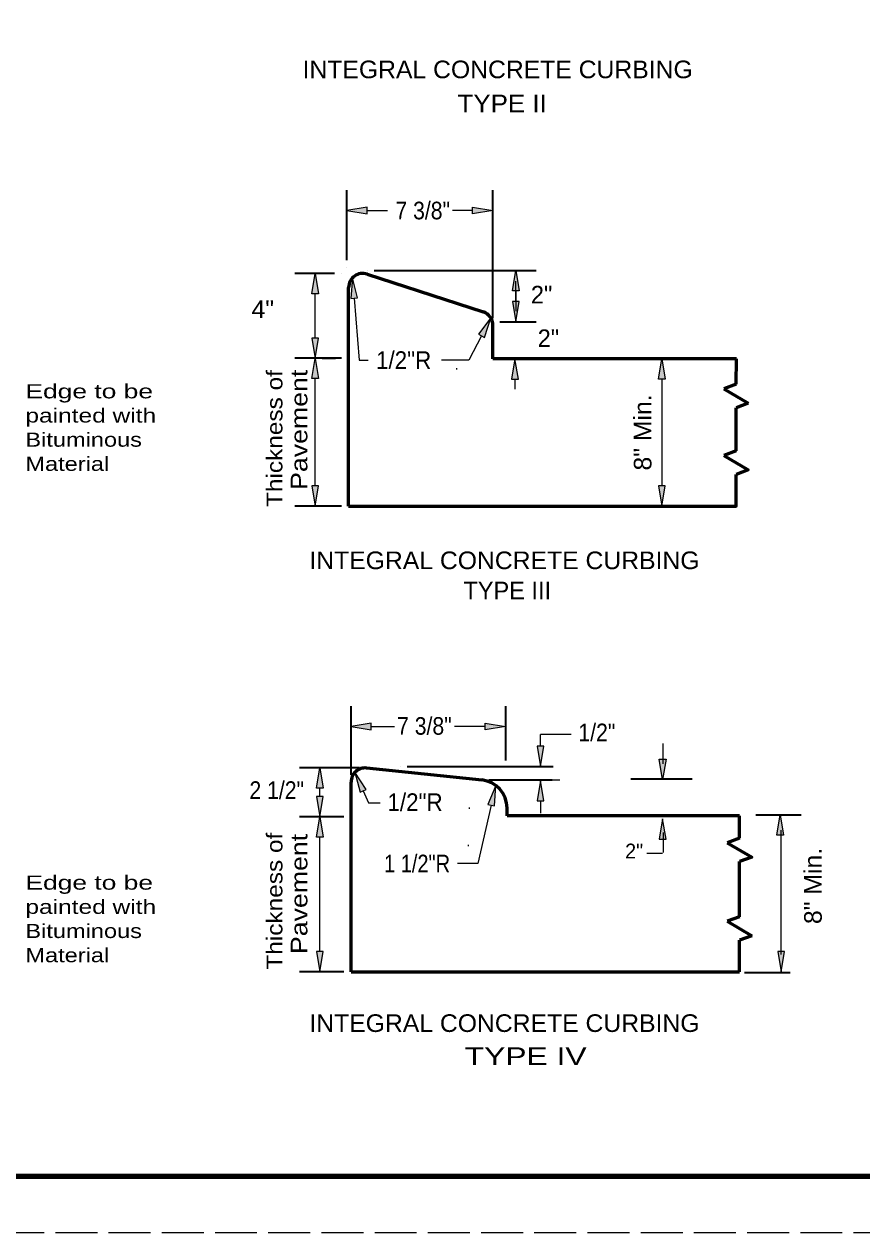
# Model space of a CAD drawing. Extents: x 36.6 to 71.9, y 0.8 to 22.8.
# Drawn here: x 47.06 to 54.49, y 0.78 to 11.49 of the extents above; entities that cross this region are included whole.
import ezdxf

# ---------------------------------------------------------------- set-up
doc = ezdxf.new("R2010")
doc.units = 0
doc.header["$LTSCALE"] = 0.062
doc.linetypes.add('LONG_DASHED', pattern=[7.5, 6, -1.5])
for name, color, linetype, lineweight in [('1', 7, 'Continuous', 13), ('3', 7, 'Continuous', 25), ('8', 7, 'Continuous', 13)]:
    doc.layers.add(name, color=color, linetype=linetype, lineweight=lineweight)

msp = doc.modelspace()

# ---------------------------------------------------------------- hatches: boundary and pattern name
at = {"layer": '1'}
for points in [[(50.10725, 9.80917), (50.10725, 9.86917), (49.92725, 9.83917), (49.92725, 9.83917)], [(51.04242, 9.80917), (51.04242, 9.86917), (51.22242, 9.83917), (51.22242, 9.83917)], [(49.67483, 9.10217), (49.61483, 9.10217), (49.64483, 9.28217), (49.64483, 9.28217)], [(51.45583, 9.12683), (51.39583, 9.12683), (51.42583, 9.30683), (51.42583, 9.30683)], [(51.45583, 9.03275), (51.39583, 9.03275), (51.42583, 8.85283), (51.42583, 8.85283)], [(49.67483, 8.70908), (49.61483, 8.70908), (49.64483, 8.529), (49.64483, 8.529)], [(49.67483, 8.34908), (49.61483, 8.34908), (49.64483, 8.529), (49.64483, 8.529)], [(52.75033, 8.34358), (52.69033, 8.34358), (52.72033, 8.52367), (52.72033, 8.52367)], [(49.67483, 7.40017), (49.61483, 7.40017), (49.64483, 7.22017), (49.64483, 7.22017)], [(52.75033, 7.40017), (52.69033, 7.40017), (52.72033, 7.22017), (52.72033, 7.22017)], [(50.14383, 5.23517), (50.14383, 5.29517), (49.96383, 5.26517), (49.96383, 5.26517)], [(51.15408, 5.23517), (51.15408, 5.29517), (51.33408, 5.26517), (51.33408, 5.26517)], [(51.67525, 5.09142), (51.61525, 5.09142), (51.64525, 4.91142), (51.64525, 4.91142)], [(52.69808, 4.97658), (52.75808, 4.97658), (52.72808, 4.79667), (52.72808, 4.79667)], [(49.71608, 4.71817), (49.65608, 4.71817), (49.68608, 4.89817), (49.68608, 4.89817)], [(51.61533, 4.60817), (51.67533, 4.60817), (51.64533, 4.78808), (51.64533, 4.78808)], [(49.71608, 4.6465), (49.65608, 4.6465), (49.68608, 4.4665), (49.68608, 4.4665)], [(49.71608, 4.2865), (49.65608, 4.2865), (49.68608, 4.4665), (49.68608, 4.4665)], [(52.69808, 4.26808), (52.75808, 4.26808), (52.72808, 4.448), (52.72808, 4.448)], [(53.80083, 4.30375), (53.74083, 4.30375), (53.77083, 4.48367), (53.77083, 4.48367)], [(49.71608, 3.27167), (49.65608, 3.27167), (49.68608, 3.09167), (49.68608, 3.09167)], [(53.80975, 3.27158), (53.74975, 3.27158), (53.77975, 3.09158), (53.77975, 3.09158)]]:
    msp.add_hatch(color=256, dxfattribs=at).paths.add_polyline_path(points)
at = {"layer": '3'}
for points in [[(49.96092, 9.05975), (50.02075, 9.06483), (49.97575, 9.24167), (49.97575, 9.24167)], [(51.09408, 8.74183), (51.14742, 8.71425), (51.20325, 8.888), (51.20325, 8.888)], [(51.38792, 8.34358), (51.44792, 8.34358), (51.41792, 8.52367), (51.41792, 8.52367)], [(50.04408, 4.68333), (50.09892, 4.70783), (49.99833, 4.86), (49.99833, 4.86)], [(51.17775, 4.57533), (51.23625, 4.56183), (51.2475, 4.74392), (51.2475, 4.74392)]]:
    msp.add_hatch(color=256, dxfattribs=at).paths.add_polyline_path(points)

# ---------------------------------------------------------------- linework, layer by layer
at = {"layer": '1', "lineweight": 35}
for p, q in [((49.92725, 9.39958), (49.92725, 10.01917)), ((51.22242, 8.884), (51.22242, 10.01917)), ((49.81767, 9.28217), (49.46483, 9.28217)), ((50.1695, 9.30683), (51.60583, 9.30683)), ((51.28492, 8.85283), (51.60583, 8.85283)), ((49.88008, 8.52908), (49.46483, 8.52908)), ((49.70733, 8.52908), (49.82483, 8.52908)), ((49.88008, 7.22017), (49.46483, 7.22017)), ((49.96383, 4.83633), (49.96383, 5.44517)), ((51.33575, 4.96508), (51.33575, 5.44517)), ((50.03933, 4.89817), (49.50608, 4.89817)), ((50.46092, 4.91142), (51.75583, 4.91142)), ((51.187, 4.79192), (51.74683, 4.79192)), ((52.44483, 4.80092), (52.99067, 4.80092)), ((49.90133, 4.4665), (49.50608, 4.4665)), ((53.95783, 4.48058), (53.55375, 4.48058)), ((49.90133, 3.09167), (49.50608, 3.09167)), ((53.85942, 3.08417), (53.45533, 3.08417))]:
    msp.add_line(p, q, dxfattribs=at)
at = {"layer": '1', "lineweight": 25}
for p, q in [((50.10725, 9.83917), (50.28725, 9.83917)), ((51.04242, 9.83917), (50.86242, 9.83917)), ((51.42583, 9.12683), (51.42583, 8.94683)), ((49.64483, 8.70908), (49.64483, 9.10217)), ((49.64483, 7.40017), (49.64483, 8.34908)), ((52.72033, 8.34367), (52.72033, 7.40017)), ((50.14383, 5.26517), (50.34825, 5.26517)), ((51.15408, 5.26517), (50.88217, 5.26517)), ((51.64525, 5.09142), (51.64525, 5.19442)), ((51.91717, 5.19442), (51.64525, 5.19442)), ((52.73117, 4.93458), (52.73117, 5.11458)), ((49.68608, 4.6465), (49.68608, 4.71817)), ((51.64525, 4.60075), (51.64525, 4.49775)), ((49.68608, 3.27167), (49.68608, 4.2865)), ((52.73117, 4.32792), (52.73117, 4.14792)), ((53.77983, 3.24383), (53.77983, 4.3485)), ((52.72742, 4.13892), (52.588, 4.13892))]:
    msp.add_line(p, q, dxfattribs=at)
at = {"layer": '1', "lineweight": 53}
for p, q in [((50.107, 9.2755), (51.13683, 8.94017)), ((49.94258, 7.22017), (49.94258, 9.15683)), ((51.22242, 8.52367), (51.22242, 8.8215)), ((53.38425, 8.52367), (51.22242, 8.52367)), ((53.37892, 8.29925), (53.38425, 8.52367)), ((53.37892, 8.29925), (53.27075, 8.25925)), ((53.27075, 8.25925), (53.48717, 8.1315)), ((53.48717, 8.1315), (53.37892, 8.09158)), ((53.37892, 7.70825), (53.37892, 8.09158)), ((53.37892, 7.70825), (53.27075, 7.66833)), ((50.10183, 4.89817), (51.1245, 4.79192)), ((49.96383, 3.09167), (49.96383, 4.77383)), ((51.34842, 4.47492), (51.34842, 4.54325)), ((53.40967, 4.47492), (51.34842, 4.47492)), ((53.40967, 4.27608), (53.40967, 4.47492)), ((53.40967, 4.27608), (53.3015, 4.23617)), ((53.40967, 3.57975), (53.40967, 4.06842)), ((53.40967, 3.57975), (53.3015, 3.53983)), ((53.3015, 3.53983), (53.51792, 3.412)), ((53.51792, 3.412), (53.40967, 3.37208)), ((53.40967, 3.09167), (53.40967, 3.37208)), ((49.96383, 3.09167), (53.40967, 3.09167))]:
    msp.add_line(p, q, dxfattribs=at)
at = {"layer": '1'}
for p, q in [((51.42583, 9.03283), (51.42583, 9.21283)), ((52.775, 8.52367), (52.90033, 8.52367)), ((52.775, 7.22017), (52.90033, 7.22017)), ((51.187, 4.79192), (51.81633, 4.79192)), ((49.74858, 4.4665), (49.86608, 4.4665)), ((51.41092, 4.47492), (51.81633, 4.47492)), ((52.80425, 4.47483), (52.92175, 4.47483)), ((52.80425, 3.09158), (52.92175, 3.09158))]:
    msp.add_line(p, q, dxfattribs=at)
at = {"layer": '1', "linetype": 'LONG_DASHED', "lineweight": 25}
msp.add_line((71.78558, 0.77842), (36.58558, 0.77842), dxfattribs=at)
at = {"layer": '1', "lineweight": 158}
msp.add_lwpolyline([(71.70225, 22.27842), (71.70225, 1.27842), (39.20225, 1.27842)], dxfattribs=at)
at = {"layer": '1'}
for points in [[(50.10725, 9.80917), (50.10725, 9.86917), (49.92725, 9.83917), (49.92725, 9.83917)], [(51.04242, 9.80917), (51.04242, 9.86917), (51.22242, 9.83917), (51.22242, 9.83917)], [(49.67483, 9.10217), (49.61483, 9.10217), (49.64483, 9.28217), (49.64483, 9.28217)], [(51.45583, 9.12683), (51.39583, 9.12683), (51.42583, 9.30683), (51.42583, 9.30683)], [(51.45583, 9.03275), (51.39583, 9.03275), (51.42583, 8.85283), (51.42583, 8.85283)], [(49.67483, 8.70908), (49.61483, 8.70908), (49.64483, 8.529), (49.64483, 8.529)], [(49.67483, 8.34908), (49.61483, 8.34908), (49.64483, 8.529), (49.64483, 8.529)], [(52.75033, 8.34358), (52.69033, 8.34358), (52.72033, 8.52367), (52.72033, 8.52367)], [(49.67483, 7.40017), (49.61483, 7.40017), (49.64483, 7.22017), (49.64483, 7.22017)], [(52.75033, 7.40017), (52.69033, 7.40017), (52.72033, 7.22017), (52.72033, 7.22017)], [(50.14383, 5.23517), (50.14383, 5.29517), (49.96383, 5.26517), (49.96383, 5.26517)], [(51.15408, 5.23517), (51.15408, 5.29517), (51.33408, 5.26517), (51.33408, 5.26517)], [(51.67525, 5.09142), (51.61525, 5.09142), (51.64525, 4.91142), (51.64525, 4.91142)], [(52.69808, 4.97658), (52.75808, 4.97658), (52.72808, 4.79667), (52.72808, 4.79667)], [(49.71608, 4.71817), (49.65608, 4.71817), (49.68608, 4.89817), (49.68608, 4.89817)], [(51.61533, 4.60817), (51.67533, 4.60817), (51.64533, 4.78808), (51.64533, 4.78808)], [(49.71608, 4.6465), (49.65608, 4.6465), (49.68608, 4.4665), (49.68608, 4.4665)], [(49.71608, 4.2865), (49.65608, 4.2865), (49.68608, 4.4665), (49.68608, 4.4665)], [(52.69808, 4.26808), (52.75808, 4.26808), (52.72808, 4.448), (52.72808, 4.448)], [(53.80083, 4.30375), (53.74083, 4.30375), (53.77083, 4.48367), (53.77083, 4.48367)], [(49.71608, 3.27167), (49.65608, 3.27167), (49.68608, 3.09167), (49.68608, 3.09167)], [(53.80975, 3.27158), (53.74975, 3.27158), (53.77975, 3.09158), (53.77975, 3.09158)]]:
    msp.add_lwpolyline(points, close=True, dxfattribs=at)
at = {"layer": '1', "lineweight": 53}
for points in [[(53.27075, 7.66833), (53.48717, 7.54058), (53.37892, 7.50067)], [(49.94258, 7.22017), (53.37892, 7.22017), (53.37892, 7.50067)], [(53.3015, 4.23617), (53.51792, 4.10842), (53.40967, 4.06842)]]:
    msp.add_lwpolyline(points, dxfattribs=at)
for centre, radius, start, end in [((50.06758, 9.15683), 0.125, 71.63873, 180), ((51.09742, 8.8215), 0.125, 0, 71.63873), ((50.08883, 4.77383), 0.125, 84.00511, 180), ((51.09842, 4.54325), 0.25, 0, 84.00511)]:
    msp.add_arc(centre, radius, start, end, dxfattribs=at)
at = {"layer": '3'}
msp.add_line((51.41792, 8.34367), (51.41792, 8.2545), dxfattribs=at)
at = {"layer": '3', "lineweight": 13}
for points in [[(49.96092, 9.05975), (50.02075, 9.06483), (49.97575, 9.24167), (49.97575, 9.24167)], [(51.09408, 8.74183), (51.14742, 8.71425), (51.20325, 8.888), (51.20325, 8.888)], [(51.38792, 8.34358), (51.44792, 8.34358), (51.41792, 8.52367), (51.41792, 8.52367)], [(50.04408, 4.68333), (50.09892, 4.70783), (49.99833, 4.86), (49.99833, 4.86)], [(51.17775, 4.57533), (51.23625, 4.56183), (51.2475, 4.74392), (51.2475, 4.74392)]]:
    msp.add_lwpolyline(points, close=True, dxfattribs=at)
at = {"layer": '3'}
for points in [[(49.99083, 9.06225), (50.03708, 8.51333), (50.11558, 8.51333)], [(51.12075, 8.72808), (51.01, 8.51333), (50.766, 8.51333)], [(50.0715, 4.69558), (50.11833, 4.59042), (50.22158, 4.59042)], [(51.207, 4.56858), (51.0875, 4.0505), (50.90942, 4.0505)]]:
    msp.add_lwpolyline(points, dxfattribs=at)
at = {"layer": '8'}
for p, q in [((51.22242, 9.83917), (51.2225, 9.83917)), ((49.92725, 9.33708), (49.92733, 9.33708)), ((49.64483, 9.28217), (49.64492, 9.28217)), ((49.88017, 9.28217), (49.88025, 9.28217)), ((50.107, 9.30683), (50.10708, 9.30683)), ((51.22242, 8.85283), (51.2225, 8.85283)), ((51.22242, 8.8215), (51.2225, 8.8215)), ((51.42583, 8.85283), (51.42592, 8.85283)), ((49.64483, 8.52908), (49.64492, 8.52908)), ((49.64483, 8.52908), (49.64492, 8.52908)), ((49.94258, 8.52908), (49.94267, 8.52908)), ((52.7125, 8.52367), (52.71258, 8.52367)), ((49.94258, 7.22017), (49.94267, 7.22017)), ((52.7125, 7.22017), (52.71258, 7.22017)), ((52.72033, 7.22017), (52.72042, 7.22017)), ((51.33408, 5.26517), (51.33417, 5.26517)), ((49.68608, 4.89817), (49.68617, 4.89817)), ((50.10183, 4.89817), (50.10192, 4.89817)), ((50.39842, 4.91142), (50.3985, 4.91142)), ((51.33575, 4.90258), (51.33583, 4.90258)), ((49.96383, 4.77383), (49.96392, 4.77383)), ((51.1245, 4.79192), (51.12458, 4.79192)), ((51.1245, 4.79192), (51.12458, 4.79192)), ((51.64525, 4.79192), (51.64533, 4.79192)), ((49.68608, 4.4665), (49.68617, 4.4665)), ((49.68608, 4.4665), (49.68617, 4.4665)), ((49.96383, 4.4665), (49.96392, 4.4665)), ((51.34842, 4.47492), (51.3485, 4.47492)), ((51.63633, 4.47492), (51.63642, 4.47492)), ((52.74175, 4.47483), (52.74183, 4.47483)), ((52.74175, 4.47483), (52.74183, 4.47483)), ((49.96383, 3.09167), (49.96392, 3.09167)), ((52.74175, 3.09158), (52.74183, 3.09158))]:
    msp.add_line(p, q, dxfattribs=at)

# ---------------------------------------------------------------- texts
at = {"layer": '1'}
for s, width, p in [('7 3/8"', 0.9, (50.3575, 9.76092)), ('4"', 1.05, (49.08125, 8.88625)), ('7 3/8"', 0.9, (50.37217, 5.19275)), ('2 1/2"', 0.9, (49.06242, 4.624))]:
    msp.add_text(s, height=0.1562, dxfattribs=dict(at, width=width)).set_placement(p)
for s, height, width, p in [('Thickness of', 0.1406, 1.15, (49.355, 7.21117)), ('8" Min.', 0.1562, 1.05, (52.6285, 7.53467)), ('Thickness of', 0.1406, 1.15, (49.355, 3.111)), ('8" Min.', 0.1562, 1.05, (54.13925, 3.51508))]:
    msp.add_text(s, height=height, rotation=90, dxfattribs=dict(at, width=width)).set_placement(p)
msp.add_text('2"', height=0.1313, dxfattribs=at).set_placement((52.39483, 4.09633))
at = {"layer": '3'}
for s, height, width, p in [('INTEGRAL CONCRETE CURBING', 0.1562, 1.05, (49.53392, 11.01167)), ('TYPE II', 0.1562, 1.1, (50.90875, 10.71025)), ('1/2"R', 0.1562, 0.95, (50.18575, 8.43525)), ('.', 0.09375, 0.9, (50.88542, 8.42933)), ('Edge to be', 0.125, 1.4, (47.07542, 8.17433)), ('painted with', 0.125, 1.3, (47.07542, 7.96017)), ('Bituminous', 0.125, 1.25, (47.07542, 7.74583)), ('Material', 0.125, 1.25, (47.07542, 7.53158)), ('INTEGRAL CONCRETE CURBING', 0.1562, 1.05, (49.59433, 6.66067)), ('1/2"', 0.1562, 0.9, (51.98067, 5.13575)), ('1/2"R', 0.1562, 0.95, (50.287, 4.51725)), ('.', 0.09375, 0.9, (50.99767, 4.53358)), ('.', 0.09375, 0.9, (50.98833, 4.20425)), ('1 1/2"R', 0.1562, 0.85, (50.25642, 3.97342)), ('Edge to be', 0.125, 1.4, (47.07542, 3.81983)), ('painted with', 0.125, 1.3, (47.07542, 3.6055)), ('Bituminous', 0.125, 1.25, (47.07542, 3.39125)), ('Material', 0.125, 1.25, (47.07542, 3.17692)), ('INTEGRAL CONCRETE CURBING', 0.1562, 1.05, (49.59433, 2.55883)), ('TYPE IV ', 0.1562, 1.35, (50.97217, 2.266))]:
    msp.add_text(s, height=height, dxfattribs=dict(at, width=width)).set_placement(p)
for s, p in [('2"', (51.55917, 9.01542)), ('2"', (51.61958, 8.62892)), ('TYPE III ', (50.96067, 6.39283))]:
    msp.add_text(s, height=0.1562, dxfattribs=at).set_placement(p)
at = {"layer": '3', "width": 1.2}
for p in [(49.5765, 7.36342), (49.5765, 3.24942)]:
    msp.add_text('Pavement', height=0.1474, rotation=90, dxfattribs=at).set_placement(p)

doc.saveas('drawing.dxf')
